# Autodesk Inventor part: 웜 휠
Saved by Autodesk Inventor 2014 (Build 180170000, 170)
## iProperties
Created: 2026-07
Part Number: 웜 휠
Material: 강철, 합금
Document SubType Name: Modeling
Designer: dg
Density: 7.85 g/cm^3
Appearance: 반연마
Mass: 499.815 g
Surface Area: 205.505 cm^2
Volume: 63.6707 cm^3
Author: jhkim
Creation Date: 2026-07-02
Sending System: Autodesk Inventor 2027
Preprocessor: ST-DEVELOPER v20.1
Author: dg
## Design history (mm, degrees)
node "웜 휠1"
node "솔리드1"
node "기준1"
